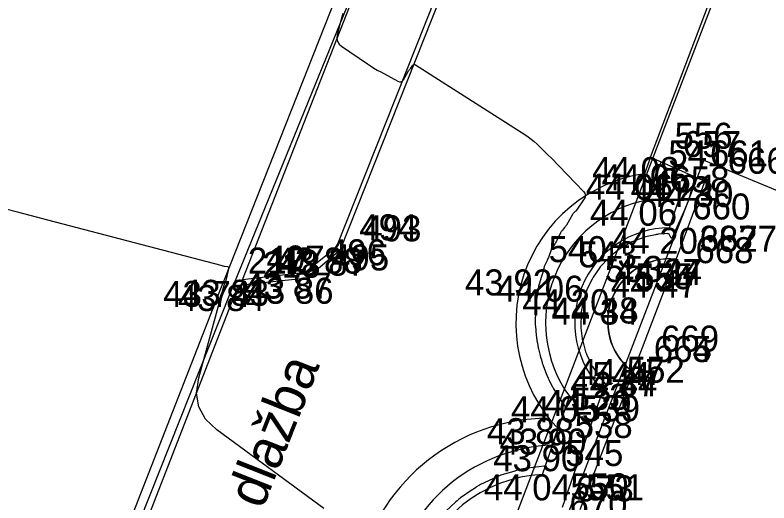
# Model space of a CAD drawing. Extents: x -702257 to -701487, y -1009871 to -1008841.
# Drawn here: x -701671.59 to -701664.34, y -1009084.05 to -1009079.36 of the extents above; entities that cross this region are included whole.
import ezdxf

# ---------------------------------------------------------------- set-up
doc = ezdxf.new("R2010")
doc.units = 0
for name, color, linetype in [('Ex_Major Contours', 7, 'Continuous'), ('Ex_Minor Contours', 7, 'Continuous'), ('Z_betonova_konstrukce', 7, 'Continuous'), ('Z_body', 7, 'Continuous'), ('Z_body_cisla', 7, 'Continuous'), ('Z_body_vysky_redukovane', 7, 'Continuous'), ('Z_budova', 7, 'Continuous'), ('Z_katastr_hranice', 7, 'Continuous'), ('Z_katastr_vnitrni_kresba', 7, 'Continuous'), ('Z_komunikace', 7, 'Continuous'), ('Z_obruba', 7, 'Continuous'), ('Z_popisy', 7, 'Continuous'), ('Z_vstupy', 7, 'Continuous')]:
    doc.layers.add(name, color=color, linetype=linetype)

# ---------------------------------------------------------------- blocks, each defined once
blk = doc.blocks.new('POINT_DISPLAY')
blk.add_line((0, 0), (0, 0))

msp = doc.modelspace()

# ---------------------------------------------------------------- linework, layer by layer
at = {"layer": 'Ex_Major Contours'}
msp.add_lwpolyline([(-701668.4386, -1009079.3488), (-701668.4472, -1009079.3834), (-701668.4558, -1009079.4179), (-701668.4903, -1009079.556), (-701668.4941, -1009079.5887), (-701668.4885, -1009079.6178), (-701668.4734, -1009079.6432), (-701668.4487, -1009079.6651), (-701668.2019, -1009079.8334), (-701668.1705, -1009079.8542), (-701668.1387, -1009079.8743), (-701668.1063, -1009079.8935), (-701668.0735, -1009079.9119), (-701667.9089, -1009080.0016), (-701667.8928, -1009080.0075), (-701667.8786, -1009080.0071), (-701667.8661, -1009080.0002), (-701667.8553, -1009079.9868), (-701667.8051, -1009079.902), (-701667.8006, -1009079.8947), (-701667.7959, -1009079.8876), (-701667.7909, -1009079.8807), (-701667.7856, -1009079.8739), (-701667.7642, -1009079.8473), (-701667.7586, -1009079.842), (-701667.7526, -1009079.8395), (-701667.746, -1009079.8399), (-701667.739, -1009079.8431), (-701666.6874, -1009080.5136), (-701666.6564, -1009080.5345), (-701666.6266, -1009080.5569), (-701666.598, -1009080.5809), (-701666.5706, -1009080.6064), (-701666.4635, -1009080.7113), (-701666.4369, -1009080.7377), (-701666.4104, -1009080.7642), (-701666.3841, -1009080.7909), (-701666.3581, -1009080.8179), (-701666.125, -1009081.0607), (-701666.1126, -1009081.0778), (-701666.1074, -1009081.0955), (-701666.1095, -1009081.1138), (-701666.1188, -1009081.1328), (-701666.1914, -1009081.2406), (-701666.1942, -1009081.2444), (-701666.1971, -1009081.248), (-701666.2003, -1009081.2514), (-701666.2038, -1009081.2546), (-701666.218, -1009081.267), (-701666.2214, -1009081.2702), (-701666.2245, -1009081.2736), (-701666.2273, -1009081.2773), (-701666.2299, -1009081.2813), (-701666.29, -1009081.3835), (-701666.294, -1009081.3901), (-701666.2984, -1009081.3964), (-701666.303, -1009081.4025), (-701666.308, -1009081.4085), (-701666.3283, -1009081.4317), (-701666.3332, -1009081.4377), (-701666.3376, -1009081.4439), (-701666.3416, -1009081.4504), (-701666.3452, -1009081.4573), (-701666.3805, -1009081.5305), (-701666.3849, -1009081.5392), (-701666.3895, -1009081.5478), (-701666.3945, -1009081.5562), (-701666.3997, -1009081.5644), (-701666.4211, -1009081.597), (-701666.4262, -1009081.6053), (-701666.4309, -1009081.6139), (-701666.435, -1009081.6226), (-701666.4386, -1009081.6317), (-701666.4585, -1009081.6852), (-701666.4624, -1009081.6953), (-701666.4665, -1009081.7052), (-701666.4708, -1009081.7151), (-701666.4753, -1009081.7249), (-701666.5031, -1009081.7834), (-701666.5044, -1009081.7868), (-701666.5204, -1009081.8479), (-701666.5232, -1009081.8582), (-701666.526, -1009081.8684), (-701666.529, -1009081.8786), (-701666.5321, -1009081.8888), (-701666.5488, -1009081.9423), (-701666.5515, -1009081.9516), (-701666.5539, -1009081.961), (-701666.5559, -1009081.9704), (-701666.5576, -1009081.98), (-701666.5651, -1009082.028), (-701666.5697, -1009082.0567), (-701666.58, -1009082.1193), (-701666.5814, -1009082.1285), (-701666.5825, -1009082.1376), (-701666.5834, -1009082.1468), (-701666.5839, -1009082.156), (-701666.5861, -1009082.2022), (-701666.5868, -1009082.2207), (-701666.587, -1009082.2299), (-701666.5889, -1009082.2974), (-701666.589, -1009082.3062), (-701666.589, -1009082.315), (-701666.5887, -1009082.3238), (-701666.5882, -1009082.3327), (-701666.5859, -1009082.3679), (-701666.5846, -1009082.3855), (-701666.5829, -1009082.4031), (-701666.5756, -1009082.4718), (-701666.5746, -1009082.4803), (-701666.5735, -1009082.4887), (-701666.5722, -1009082.4971), (-701666.5708, -1009082.5055), (-701666.5648, -1009082.5389), (-701666.5632, -1009082.5472), (-701666.5615, -1009082.5555), (-701666.5597, -1009082.5638), (-701666.5578, -1009082.5721), (-701666.5418, -1009082.6388), (-701666.5377, -1009082.6548), (-701666.5332, -1009082.6706), (-701666.5237, -1009082.7021), (-701666.5212, -1009082.7099), (-701666.5186, -1009082.7177), (-701666.5159, -1009082.7255), (-701666.5131, -1009082.7332), (-701666.4898, -1009082.7952), (-701666.484, -1009082.8102), (-701666.4778, -1009082.825), (-701666.465, -1009082.8545), (-701666.4617, -1009082.8619), (-701666.4583, -1009082.8692), (-701666.4548, -1009082.8764), (-701666.4512, -1009082.8836), (-701666.4226, -1009082.9387), (-701666.4151, -1009082.9528), (-701666.4074, -1009082.9667), (-701666.3915, -1009082.9943), (-701666.3875, -1009083.0012), (-701666.3834, -1009083.008), (-701666.3791, -1009083.0147), (-701666.3747, -1009083.0214), (-701666.3432, -1009083.0684), (-701666.3342, -1009083.0815), (-701666.3249, -1009083.0946), (-701666.3061, -1009083.1204), (-701666.3023, -1009083.127), (-701666.3003, -1009083.1339), (-701666.3002, -1009083.141), (-701666.3019, -1009083.1484), (-701666.4731, -1009083.6428), (-701666.4793, -1009083.66), (-701666.49, -1009083.6886), (-701666.4926, -1009083.6937), (-701666.4962, -1009083.6975), (-701666.5008, -1009083.7001), (-701666.5064, -1009083.7014), (-701666.5556, -1009083.7072), (-701666.5818, -1009083.7105), (-701666.6876, -1009083.7243), (-701666.6966, -1009083.7257), (-701666.7056, -1009083.7273), (-701666.7145, -1009083.7293), (-701666.7234, -1009083.7316), (-701666.7674, -1009083.7437), (-701666.7938, -1009083.7512), (-701666.9094, -1009083.7847), (-701666.9183, -1009083.7875), (-701666.927, -1009083.7908), (-701666.9486, -1009083.7997), (-701666.9571, -1009083.8036), (-701666.9825, -1009083.8163), (-701666.9952, -1009083.8224), (-701667.1154, -1009083.8788), (-701667.1239, -1009083.883), (-701667.1321, -1009083.8877), (-701667.1524, -1009083.9002), (-701667.1603, -1009083.9054), (-701667.1834, -1009083.9222), (-701667.1951, -1009083.9304), (-701667.3064, -1009084.0061), (-701667.3141, -1009084.0117), (-701667.3215, -1009084.0177), (-701667.3395, -1009084.0333), (-701667.3501, -1009084.0429), (-701667.4478, -1009084.1354)], dxfattribs=at)
at = {"layer": 'Ex_Minor Contours'}
for points in [[(-701665.0544, -1009080.9267), (-701665.1111, -1009081.1204), (-701665.1211, -1009081.1525), (-701665.1321, -1009081.1842), (-701665.1443, -1009081.2155), (-701665.1575, -1009081.2464), (-701665.2726, -1009081.5037), (-701665.2756, -1009081.5088), (-701665.2788, -1009081.5105), (-701665.282, -1009081.509), (-701665.2854, -1009081.5041), (-701665.299, -1009081.478), (-701665.3029, -1009081.4723), (-701665.3078, -1009081.4685), (-701665.3137, -1009081.4664), (-701665.3205, -1009081.466), (-701665.4066, -1009081.4725), (-701665.4153, -1009081.4734), (-701665.4282, -1009081.475), (-701665.4325, -1009081.4759), (-701665.5304, -1009081.4977), (-701665.539, -1009081.4999), (-701665.5518, -1009081.5037), (-701665.556, -1009081.5052), (-701665.6519, -1009081.5421), (-701665.6601, -1009081.5456), (-701665.6721, -1009081.5515), (-701665.6761, -1009081.5537), (-701665.7666, -1009081.6052), (-701665.7741, -1009081.61), (-701665.7867, -1009081.6191), (-701665.7885, -1009081.6205), (-701665.8704, -1009081.6852), (-701665.8769, -1009081.691), (-701665.8892, -1009081.7035), (-701665.9598, -1009081.779), (-701665.9652, -1009081.7856), (-701665.975, -1009081.7995), (-701666.0326, -1009081.883), (-701666.0365, -1009081.8896), (-701666.0434, -1009081.9033), (-701666.0889, -1009081.9951), (-701666.0954, -1009082.0154), (-701666.119, -1009082.087), (-701666.1229, -1009082.0997), (-701666.1264, -1009082.1124), (-701666.1294, -1009082.1253), (-701666.1319, -1009082.1383), (-701666.146, -1009082.218), (-701666.1484, -1009082.2348), (-701666.1489, -1009082.2412), (-701666.1517, -1009082.3445), (-701666.1517, -1009082.3533), (-701666.1513, -1009082.3664), (-701666.1509, -1009082.3708), (-701666.138, -1009082.4743), (-701666.1366, -1009082.4831), (-701666.134, -1009082.4962), (-701666.1329, -1009082.5005), (-701666.1046, -1009082.6008), (-701666.1019, -1009082.6093), (-701666.0971, -1009082.6219), (-701666.0953, -1009082.626), (-701666.0529, -1009082.7195), (-701666.0489, -1009082.7275), (-701666.041, -1009082.7409), (-701666.0398, -1009082.7428), (-701665.9854, -1009082.827), (-701665.9803, -1009082.834), (-701665.9691, -1009082.8474), (-701665.913, -1009082.9117), (-701665.9076, -1009082.9166), (-701665.9016, -1009082.9193), (-701665.895, -1009082.9198), (-701665.8879, -1009082.9182), (-701665.8436, -1009082.9021)], [(-701668.6195, -1009084.1084), (-701669.6489, -1009083.3513), (-701669.7566, -1009083.2488), (-701669.8214, -1009083.1314), (-701669.8432, -1009082.9991), (-701669.822, -1009082.8519), (-701669.5665, -1009081.9259), (-701669.5645, -1009081.9227), (-701669.5603, -1009081.9187), (-701669.5595, -1009081.917), (-701669.5319, -1009081.8039), (-701669.5312, -1009081.797), (-701669.533, -1009081.7917), (-701669.5371, -1009081.788), (-701669.5436, -1009081.7858), (-701669.5746, -1009081.7803), (-701669.5824, -1009081.7789), (-701669.5901, -1009081.7773), (-701669.5977, -1009081.7755), (-701669.6054, -1009081.7736), (-701671.27, -1009081.3369), (-701671.5501, -1009081.2637), (-701671.8302, -1009081.1908)]]:
    msp.add_lwpolyline(points, dxfattribs=at)
at = {"layer": 'Z_betonova_konstrukce'}
for p, q in [((-701665.48, -1009080.73), (-701665.54, -1009080.89)), ((-701665.39, -1009080.8), (-701665.38, -1009080.78)), ((-701665.5, -1009081.14), (-701665.39, -1009080.8)), ((-701665.3, -1009081.41), (-701665.13, -1009080.9)), ((-701665.13, -1009080.9), (-701665.13, -1009080.9)), ((-701666.52, -1009083.78), (-701666.26, -1009083.03)), ((-701665.94, -1009082.97), (-701666.33, -1009084.1)), ((-701666.43, -1009083.5), (-701666.37, -1009083.34))]:
    msp.add_line(p, q, dxfattribs=at)
for centre, radius, start, end in [((-701665.2961, -1009082.3229), 0.9129, 90.24327, 225.14432), ((-701665.2884, -1009082.312), 0.6039, 85.40633, 230.80632), ((-701666.3628, -1009085.141), 1.6424, 92.34671, 236.46766), ((-701666.4452, -1009085.1201), 1.3422, 93.19281, 235.78309)]:
    msp.add_arc(centre, radius, start, end, dxfattribs=at)
for centre, major_axis, ratio, start_param, end_param in [((-701665.3222, -1009082.3329), (-0.4675, 1.3826), 0.994854, 6.106091, 8.29154), ((-701665.2858, -1009082.3239), (-0.9345, -0.7579), 0.999949, 4.209949, 6.228847), ((-701665.2935, -1009082.3099), (0.2246, 0.5589), 0.999727, 0.293276, 2.848317), ((-701666.451, -1009085.128), (-0.6622, 1.7685), 0.998356, 5.93445, 8.550797)]:
    msp.add_ellipse(centre, major_axis=major_axis, ratio=ratio, start_param=start_param, end_param=end_param, dxfattribs=at)
at = {"layer": 'Z_budova'}
for p, q in [((-701665.48, -1009080.73), (-701662.38, -1009072.56)), ((-701665.48, -1009080.73), (-701664.96, -1009080.96)), ((-701664.96, -1009080.96), (-701665.28, -1009081.83)), ((-701665.6, -1009082.67), (-701666.16, -1009084.12))]:
    msp.add_line(p, q, dxfattribs=at)
at = {"layer": 'Z_katastr_hranice'}
for p, q in [((-701661.01, -1009069.12), (-701665.49, -1009080.82)), ((-701669.52, -1009082.04), (-701664.86, -1009070.6)), ((-701665.49, -1009080.82), (-701668.63, -1009089.02)), ((-701670.9, -1009085.52), (-701669.52, -1009082.04))]:
    msp.add_line(p, q, dxfattribs=at)
at = {"layer": 'Z_katastr_vnitrni_kresba'}
for q in [(-701668.13, -1009088.98), (-701657.66, -1009083.78)]:
    msp.add_line((-701664.97, -1009080.76), q, dxfattribs=at)
at = {"layer": 'Z_komunikace'}
for p in [(-701665.95, -1009072.72), (-701673.36, -1009091.61)]:
    msp.add_line(p, (-701669.58, -1009081.92), dxfattribs=at)
at = {"layer": 'Z_obruba'}
for p, q in [((-701669.4, -1009081.91), (-701665.83, -1009072.77)), ((-701667.25, -1009078.44), (-701668.5, -1009081.6)), ((-701668.46, -1009081.62), (-701667.21, -1009078.46)), ((-701668.5, -1009081.6), (-701668.8, -1009081.84)), ((-701668.78, -1009081.89), (-701668.46, -1009081.62)), ((-701668.8, -1009081.84), (-701669.4, -1009081.91)), ((-701669.44, -1009081.96), (-701668.78, -1009081.89)), ((-701670.79, -1009085.43), (-701669.44, -1009081.96))]:
    msp.add_line(p, q, dxfattribs=at)
at = {"layer": 'Z_vstupy'}
msp.add_line((-701665.6, -1009082.67), (-701665.28, -1009081.83), dxfattribs=at)

# ---------------------------------------------------------------- block references
at = {"layer": 'Z_body'}
for p in [(-701665.48, -1009080.73), (-701665.39, -1009080.8), (-701665.54, -1009080.89), (-701665.13, -1009080.9), (-701664.96, -1009080.96), (-701665.5, -1009081.14), (-701665.3, -1009081.41), (-701668.5, -1009081.6), (-701668.46, -1009081.62), (-701665.24, -1009081.71), (-701665.24, -1009081.71), (-701668.8, -1009081.84), (-701666.68, -1009081.81), (-701666.4, -1009081.87), (-701665.28, -1009081.83), (-701669.58, -1009081.92), (-701669.4, -1009081.91), (-701668.78, -1009081.89), (-701669.44, -1009081.96), (-701666.15, -1009082), (-701665.85, -1009082.08), (-701665.85, -1009082.09), (-701665.6, -1009082.67), (-701665.67, -1009082.78), (-701665.67, -1009082.78), (-701666.26, -1009083.03), (-701665.94, -1009082.97), (-701666.47, -1009083.24), (-701666.37, -1009083.34), (-701666.43, -1009083.5), (-701666.52, -1009083.78)]:
    msp.add_blockref('POINT_DISPLAY', p, dxfattribs=at)

# ---------------------------------------------------------------- texts
at = {"layer": 'Z_body_cisla'}
for s, p in [('556', (-701665.25, -1009080.65)), ('657', (-701665.17, -1009080.73)), ('541', (-701665.31, -1009080.82)), ('661', (-701664.91, -1009080.82)), ('666', (-701664.74, -1009080.89)), ('658', (-701665.28, -1009081.07)), ('660', (-701665.08, -1009081.33)), ('494', (-701668.28, -1009081.53)), ('493', (-701668.24, -1009081.54)), ('3877', (-701665.01, -1009081.64)), ('662', (-701665.01, -1009081.64)), ('496', (-701668.58, -1009081.77)), ('540', (-701666.46, -1009081.74)), ('668', (-701665.05, -1009081.75)), ('497', (-701669.17, -1009081.83)), ('495', (-701668.55, -1009081.82)), ('543', (-701666.17, -1009081.79)), ('217', (-701669.35, -1009081.85)), ('218', (-701669.21, -1009081.89)), ('553', (-701665.92, -1009081.93)), ('555', (-701665.63, -1009082)), ('554', (-701665.63, -1009082.02)), ('669', (-701665.38, -1009082.6)), ('664', (-701665.45, -1009082.7)), ('665', (-701665.45, -1009082.7)), ('552', (-701665.71, -1009082.9)), ('544', (-701666.04, -1009082.95)), ('533', (-701666.25, -1009083.16)), ('539', (-701666.14, -1009083.27)), ('538', (-701666.21, -1009083.43)), ('545', (-701666.3, -1009083.7)), ('550', (-701666.25, -1009084.02)), ('673', (-701666.2, -1009084.04)), ('551', (-701666.1, -1009084.03)), ('670', (-701666.26, -1009084.19))]:
    msp.add_text(s, height=0.25, dxfattribs=at).set_placement(p)
at = {"layer": 'Z_body_vysky_redukovane'}
for s, p in [('44 08', (-701666.0425, -1009080.98)), ('44 06', (-701665.9525, -1009081.05)), ('44 06', (-701666.1025, -1009081.14)), ('44 21', (-701665.6717, -1009081.15)), ('44 30', (-701665.5225, -1009081.21)), ('44 06', (-701666.0625, -1009081.39)), ('44 20', (-701665.8625, -1009081.66)), ('43 88', (-701669.0833, -1009081.85)), ('43 87', (-701669.0433, -1009081.87)), ('44 34', (-701665.8233, -1009081.96)), ('44 47', (-701665.8233, -1009081.96)), ('43 92', (-701667.2633, -1009082.06)), ('43 87', (-701669.3833, -1009082.09)), ('44 06', (-701666.9625, -1009082.12)), ('44 47', (-701665.8633, -1009082.08)), ('43 74', (-701670.1633, -1009082.17)), ('43 83', (-701669.9833, -1009082.16)), ('43 86', (-701669.3633, -1009082.14)), ('43 84', (-701670.0233, -1009082.21)), ('44 20', (-701666.7125, -1009082.25)), ('44 48', (-701666.4333, -1009082.33)), ('44 34', (-701666.4333, -1009082.34)), ('44 47', (-701666.1833, -1009082.92)), ('44 34', (-701666.2533, -1009083.03)), ('44 47', (-701666.2533, -1009083.03)), ('44 05', (-701666.8225, -1009083.28)), ('44 20', (-701666.5025, -1009083.22)), ('43 88', (-701667.0533, -1009083.49)), ('43 90', (-701666.9325, -1009083.59)), ('43 90', (-701666.9925, -1009083.75)), ('44 04', (-701667.0825, -1009084.03))]:
    msp.add_text(s, height=0.25, dxfattribs=at).set_placement(p)
at = {"layer": 'Z_popisy'}
msp.add_text('zám. dlažba', height=0.38, rotation=68.4, dxfattribs=at).set_placement((-701669.666, -1009085.279))

doc.saveas('drawing.dxf')
